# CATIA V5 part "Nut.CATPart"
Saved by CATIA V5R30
Part number: nut
Bounding box of the stored display mesh (mm): x -13.856 to 13.856, y 0 to 9, z -12 to 12
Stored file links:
  D:\PROJECTS\CATIA V56R 2020\Resources\Parts File\c14_catia_v5_6r2020_prt\c14-catia-v5-6r2020-figr-14-26 & 27\Part & Asm\Nut.CATPart
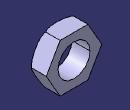
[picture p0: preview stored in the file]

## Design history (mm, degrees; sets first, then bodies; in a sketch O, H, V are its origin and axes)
Body1 (main body)
  Sketch1 on zx-plane, origin (0, 0, 0), H (-1, 0, 0), V (0, 0, 1)
    circle A1 centre (0, 0) radius 8
    construction circle A2 centre (0, 0) radius 12
    point P1 (-6.9282, -12)
    point P2 (6.9282, -12)
    point P3 (13.8564, 0)
    point P4 (6.9282, 12)
    point P5 (-6.9282, 12)
    point P6 (-13.8564, 0)
    point P7 (0, -12)
    line L1 (-6.9282, -12) -> (6.9282, -12)
    line L2 (6.9282, -12) -> (13.8564, 0)
    line L3 (13.8564, 0) -> (6.9282, 12)
    line L4 (6.9282, 12) -> (-6.9282, 12)
    line L5 (-6.9282, 12) -> (-13.8564, 0)
    line L6 (-13.8564, 0) -> (-6.9282, -12)
    construction line L7 (0, 0) -> (0, -12)
    construction circle A3 centre (0, 0) radius 13.8564
    construction arc A4 centre (-6.9282, 12) radius 13.8564 from (6.9282, 12) to (-13.8564, 0) cw
    construction arc A5 centre (6.9282, -12) radius 13.8564 from (13.8564, 0) to (-6.9282, -12) ccw
    radius A1 = 8
    radius A2 = 12
    coincidence: P7 A2, A3 P1, A3 P2, A3 P3, A3 P4, A3 P5, A3 P6, A4 O, A5 O
    vertical: L7 V
    midpoint: P7 L1
    parallelism: L1 L4
  Pad1: profile Sketch1, direction (0, 1, 0), length 9
  Sketch2 on xy-plane, origin (0, 0, 0), H (1, 0, 0), V (0, 1, 0)
    projected line E1 (10.7061, 0) -> (13.8564, 0) from edge of Pad1
    point P1 (13.8564, 0)
    projected line E2 (13.8564, 0) -> (13.8564, 1.8188) from edge of Pad1
    point P2 (13.8564, 0)
    arc A1 centre (10.7061, 3.6376) radius 3.6376 from (10.7061, 0) to (13.8564, 1.8188) ccw
    coincidence: P1 P2
    tangency: A1 E1
  Groove1: profile Sketch2, axis axis of face of Pad1, angle 360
